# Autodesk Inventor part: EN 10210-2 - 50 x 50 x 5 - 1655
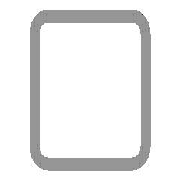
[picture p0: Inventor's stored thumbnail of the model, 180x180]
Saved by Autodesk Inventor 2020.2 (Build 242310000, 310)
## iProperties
Created: 2019-01
Part Number: EN 10210-2 - 50 x 50 x 5 - 1655
Material: Stahl, weich
Description: Rohrleitung
Document SubType Name: Modeling
Standard: DIN
Designer: lutzd
Standard Revision: 2006-07
Standards Organization: DIN
Language: de-DE
Size Designation: 50 x 50 x 5
Categories: <MemberInstance><Categories><Category DisplayName="Profile" InternalName="089c4875-fa83-4c05-b084-43b9cc11f5ed" Mnemonic="GRDR"><CategoryParameter DisplayName="
Stock Number: 50 x 50 x 5
Mass: 11344.1 g
Surface Area: 5620.3 cm^2
Volume: 1445.1 cm^3
Density: 7.85 g/cm^3
Appearance: Semi-Polished(8)
IsCustomPart: 1
_CCFamilyMember: 16
_CCFamilyDisplayName: DIN EN 10210-2 (USAS B17.1 quadratisch) - Rohrleitung — In Klammern angegebene Größen wurden aufgehoben
_FrameMemberDoc: Frame Member File
_Version: 15.0.0
_GetPNFromCC: 1
G_L: 1655,000 mm
G_W: 50,000 mm
G_H: 50,000 mm
DocNumber: ADSK-014274
Folder: .
Dimensions: 50x50x1655 mm
Mass: 11,344 kg
+FA17F10E-FEC8-4A26-9AEA-59EB1BC1EBFA+SCHNITTDETAIL1: Schnittwinkel 90,00 grd
VLT_Material: Stahl, weich
Title: Profil-Bauteil
Author: lutzd
Revision Number: -
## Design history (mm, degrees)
node "Startebene"
node "Endebene"
sketch "Skizze"
  geometry: L1 (-25, -17.5)-(-25, 17.5); L2 (-17.5, 25)-(17.5, 25); L3 (25, 17.5)-(25, -17.5); L4 (17.5, -25)-(-17.5, -25); L5 (-15, 20)-(15, 20); L6 (20, 15)-(20, -15); L7 (15, -20)-(-15, -20); L8 (-20, -15)-(-20, 15); L9 (0, 37.175)-(0, -37.175) reference; L10 (-37.175, 0)-(37.175, 0) reference; A1 r 7.5 centre (-17.5, -17.5) between (-25, -17.5) and (-17.5, -25); A2 r 7.5 centre (-17.5, 17.5) between (-17.5, 25) and (-25, 17.5); A3 r 7.5 centre (17.5, 17.5) between (25, 17.5) and (17.5, 25); A4 r 7.5 centre (17.5, -17.5) between (17.5, -25) and (25, -17.5); A5 r 5 centre (-15, -15) between (-20, -15) and (-15, -20); A6 r 5 centre (-15, 15) between (-15, 20) and (-20, 15); A7 r 5 centre (15, 15) between (20, 15) and (15, 20); A8 r 5 centre (15, -15) between (15, -20) and (20, -15)
  constraints: 16 end point, 16 point on circle, 16 tangent, 8 centre point, 6 equal radius, 4 parallel, 2 perpendicular, 2 other
  dimensions: "d7" = 7.5 radius of A1 (= G_IR); "d10" = 50 distance between parallel lines of L2 L4 (= G_H); "d11" = 50 distance between parallel lines of L1 L3 (= G_W); "d12" = 5 distance between parallel lines of L3 L6 (= G_T); "d15" = 25 distance between parallel lines of L2 L10 (= 0.5 x d10); "d16" = 25 distance between parallel lines of L9 L3 (= 0.5 x d11); "d19" = 5 radius of A5 (= G_T); "d20" = 5 distance between parallel lines of L4 L7 (= G_T)
extrude "Körper" new body sketch "Skizze" stored distance "d3" = 1655 (= G_L); taper "d4" = 0 deg
node "Driven Length"
  sketch "Sketch3"
    geometry: L1 (0, 0)-(10, 0) reference
    constraints: 2 end point, 1 horizontal
  workplane "Work Plane3"
  sketch "Sketch4"
    geometry: L1 (-2, 50)-(12, 50) reference; L2 (-2, 1705)-(12, 1705) reference
    dimensions: "d18" = 1655 distance between parallel lines of L1 L2 (derived)
workplane "Arbeitsebene4"
feature "Trennen1"
body "Solid1"
other parameters: "G_W" = 50 [user parameter; used in 1 equation term], "G_H" = 50 [user parameter; used in 1 equation term], "G_T" = 5 [user parameter; used in 3 equation terms], "G_IR" = 7.5 [user parameter; used in 1 equation term], "G_L" = 1655 (= d18) [user parameter; used in 1 equation term], "G_OFFSET_END" = 0 [user parameter; used in 1 equation term], "d14" = 1705 (= G_OFFSET_END + B_L), "B_L" = 1705 [user parameter; used in 1 equation term], "d17" = 90 deg
